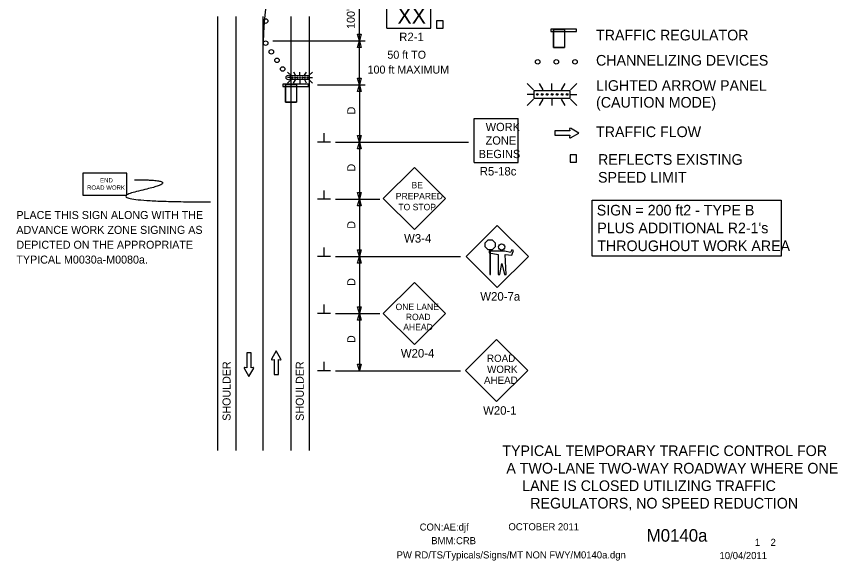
# Model space of a CAD drawing. Extents: x 16738 to 18485, y 7217 to 8213.
# Drawn here: x 16738 to 17456, y 7218 to 7694 of the extents above; entities that cross this region are included whole.
import ezdxf

# ---------------------------------------------------------------- set-up
doc = ezdxf.new("R2010")
doc.units = 0
for name, color, linetype in [('ALI_LEGAL_EX', 7, 'Continuous'), ('BORDER', 7, 'Continuous'), ('BORDER_SIGNAL_WO', 7, 'Continuous'), ('MT_SCRATCH_LEVEL_E', 7, 'Continuous'), ('PAVT_EDGE_EX', 7, 'Continuous'), ('TRAFFIC_SIGNS_PR', 7, 'Continuous'), ('TYPICAL_TEXT_DIMEN_EX', 7, 'Continuous'), ('TYPICAL_TEXT_DIMEN_PR', 7, 'Continuous')]:
    doc.layers.add(name, color=color, linetype=linetype)

msp = doc.modelspace()

# ---------------------------------------------------------------- linework, layer by layer
at = {"layer": 'ALI_LEGAL_EX'}
msp.add_line((16953.95, 7314.41), (16953.95, 7671.03), dxfattribs=at)
msp.add_line((16953.95, 7314.41), (16953.95, 7671.03), dxfattribs=at)
msp.add_arc((17174.73, 7671.79), 220.78, 142.68987, 180.19827, dxfattribs=at)
at = {"layer": 'MT_SCRATCH_LEVEL_E'}
for p, q in [((17222.13, 7593.96), (17208.87, 7593.96)), ((17208.87, 7593.96), (17208.87, 7590.22)), ((17222.13, 7593.96), (17208.87, 7593.96)), ((17208.87, 7593.96), (17208.87, 7590.22)), ((17221.81, 7595.74), (17222.13, 7593.96)), ((17221.81, 7595.74), (17222.13, 7593.96)), ((17229.74, 7592.11), (17222.5, 7596.22)), ((17229.74, 7592.11), (17222.5, 7596.22)), ((17222.5, 7587.96), (17229.74, 7592.11)), ((17222.5, 7587.96), (17229.74, 7592.11)), ((17208.87, 7590.22), (17222.13, 7590.22)), ((17208.87, 7590.22), (17222.13, 7590.22)), ((17222.13, 7590.22), (17221.81, 7588.44)), ((17222.13, 7590.22), (17221.81, 7588.44)), ((16943.27, 7399.92), (16939.52, 7399.92)), ((16939.52, 7399.92), (16939.52, 7386.67)), ((16943.27, 7399.92), (16939.52, 7399.92)), ((16939.52, 7399.92), (16939.52, 7386.67)), ((16943.27, 7386.67), (16943.27, 7399.92)), ((16943.27, 7386.67), (16943.27, 7399.92)), ((16965.24, 7401.61), (16961.12, 7394.37)), ((16965.24, 7401.61), (16961.12, 7394.37)), ((16969.38, 7394.37), (16965.24, 7401.61)), ((16969.38, 7394.37), (16965.24, 7401.61)), ((16961.61, 7393.69), (16963.38, 7394)), ((16961.61, 7393.69), (16963.38, 7394)), ((16963.38, 7394), (16963.38, 7380.74)), ((16963.38, 7394), (16963.38, 7380.74)), ((16967.12, 7380.74), (16967.12, 7394)), ((16967.12, 7394), (16968.9, 7393.69)), ((16967.12, 7380.74), (16967.12, 7394)), ((16967.12, 7394), (16968.9, 7393.69)), ((16937.27, 7386.3), (16941.41, 7379.06)), ((16937.27, 7386.3), (16941.41, 7379.06)), ((16939.52, 7386.67), (16937.75, 7386.98)), ((16939.52, 7386.67), (16937.75, 7386.98)), ((16941.41, 7379.06), (16945.53, 7386.3)), ((16941.41, 7379.06), (16945.53, 7386.3)), ((16945.04, 7386.98), (16943.27, 7386.67)), ((16945.04, 7386.98), (16943.27, 7386.67)), ((16963.38, 7380.74), (16967.12, 7380.74)), ((16963.38, 7380.74), (16967.12, 7380.74))]:
    msp.add_line(p, q, dxfattribs=at)
for centre, start, end in [((17222.27, 7595.81), 60.42484, 189.96381), ((17222.27, 7595.81), 60.42484, 189.96381), ((17222.27, 7588.37), 170.03619, 299.77312), ((17222.27, 7588.37), 170.03619, 299.77312), ((16961.53, 7394.15), 150.42484, 279.96381), ((16961.53, 7394.15), 150.42484, 279.96381), ((16968.97, 7394.15), 260.03619, 29.77312), ((16968.97, 7394.15), 260.03619, 29.77312), ((16937.68, 7386.52), 80.03619, 209.77312), ((16937.68, 7386.52), 80.03619, 209.77312), ((16945.12, 7386.52), 330.42484, 99.96381), ((16945.12, 7386.52), 330.42484, 99.96381)]:
    msp.add_arc(centre, 0.463, start, end, dxfattribs=at)
at = {"layer": 'PAVT_EDGE_EX'}
for p, q in [((16913.95, 7694.12), (16913.95, 7314.41)), ((16929.95, 7694.12), (16929.95, 7314.41)), ((16953.95, 7314.41), (16953.95, 7694.12)), ((16977.95, 7694.12), (16977.95, 7314.41)), ((16993.95, 7694.12), (16993.95, 7314.41))]:
    msp.add_line(p, q, dxfattribs=at)
for points in [[(16953.95, 7614.41), (16953.95, 7639.41)], [(16953.95, 7514.41), (16953.95, 7539.41)], [(16953.95, 7414.41), (16953.95, 7439.41)], [(16953.95, 7314.41), (16953.95, 7339.41)]]:
    msp.add_lwpolyline(points, dxfattribs=at)
at = {"layer": 'TRAFFIC_SIGNS_PR'}
for p, q in [((17062.1, 7683.95), (17062.1, 7731.95)), ((17100.5, 7683.95), (17100.5, 7731.95)), ((17062.1, 7683.95), (17100.5, 7683.95)), ((17207.84, 7682.59), (17207.84, 7666.99)), ((17217.43, 7682.59), (17217.43, 7666.99)), ((17207.84, 7666.99), (17217.43, 7666.99)), ((16975.05, 7645.45), (16977.87, 7642.64)), ((16982.14, 7642.64), (16980.51, 7645.46)), ((16985.95, 7642.64), (16985.95, 7645.46)), ((16990.09, 7642.64), (16991.71, 7645.46)), ((16994.04, 7642.64), (16996.86, 7645.46)), ((16973.43, 7634.58), (16973.43, 7618.97)), ((16977.87, 7640.61), (16975.05, 7640.61)), ((16975.05, 7635.76), (16977.87, 7638.57)), ((16979.5, 7640.61), (16979.5, 7640.61)), ((16980.48, 7635.75), (16982.11, 7638.57)), ((16981.68, 7640.61), (16981.68, 7640.61)), ((16983.01, 7634.58), (16983.01, 7618.97)), ((16983.85, 7640.61), (16983.85, 7640.61)), ((16985.95, 7638.57), (16985.95, 7635.75)), ((16986.03, 7640.61), (16986.03, 7640.61)), ((16988.2, 7640.61), (16988.2, 7640.61)), ((16991.74, 7635.75), (16990.11, 7638.57)), ((16990.37, 7640.61), (16990.37, 7640.61)), ((16992.55, 7640.61), (16992.55, 7640.61)), ((16994.04, 7640.61), (16996.86, 7640.61)), ((16994.04, 7638.57), (16996.86, 7635.75)), ((17184.6, 7635.55), (17190.23, 7629.92)), ((17198.77, 7629.92), (17195.51, 7635.56)), ((17206.4, 7629.92), (17206.4, 7635.56)), ((17214.67, 7629.92), (17217.93, 7635.56)), ((17222.57, 7629.92), (17228.22, 7635.56)), ((17190.23, 7625.85), (17184.6, 7625.85)), ((17184.6, 7616.15), (17190.23, 7621.79)), ((17193.51, 7625.85), (17193.51, 7625.85)), ((17195.47, 7616.15), (17198.72, 7621.79)), ((17197.86, 7625.85), (17197.86, 7625.85)), ((17202.2, 7625.85), (17202.2, 7625.85)), ((17206.4, 7621.79), (17206.4, 7616.15)), ((17206.55, 7625.85), (17206.55, 7625.85)), ((17210.9, 7625.85), (17210.9, 7625.85)), ((17217.98, 7616.15), (17214.72, 7621.79)), ((17215.25, 7625.85), (17215.25, 7625.85)), ((17219.59, 7625.85), (17219.59, 7625.85)), ((17222.57, 7625.85), (17228.22, 7625.85)), ((17222.57, 7621.79), (17228.22, 7616.15)), ((16973.43, 7618.97), (16983.01, 7618.97)), ((17138.41, 7566.43), (17138.41, 7604.83)), ((17138.41, 7604.83), (17176.81, 7604.83)), ((17176.81, 7566.43), (17176.81, 7604.83)), ((17086.05, 7562.01), (17058.9, 7534.85)), ((17113.21, 7534.85), (17086.05, 7562.01)), ((17138.41, 7566.43), (17176.81, 7566.43)), ((17058.9, 7534.85), (17086.05, 7507.7)), ((17086.05, 7507.7), (17113.21, 7534.85)), ((17158.57, 7511.24), (17131.42, 7484.08)), ((17185.72, 7484.08), (17158.57, 7511.24)), ((17131.42, 7484.08), (17158.57, 7456.93)), ((17158.57, 7456.93), (17185.72, 7484.08)), ((17086.05, 7461.49), (17058.9, 7434.34)), ((17113.21, 7434.34), (17086.05, 7461.49)), ((17058.9, 7434.34), (17086.05, 7407.18)), ((17086.05, 7407.18), (17113.21, 7434.34)), ((17158, 7411.45), (17130.85, 7384.3)), ((17185.15, 7384.3), (17158, 7411.45)), ((17130.85, 7384.3), (17158, 7357.15)), ((17158, 7357.15), (17185.15, 7384.3))]:
    msp.add_line(p, q, dxfattribs=at)
for points in [[(17105.51, 7683.95), (17111.11, 7683.95), (17111.11, 7690.12), (17105.51, 7690.12)], [(17227.83, 7682.92), (17205.45, 7682.92), (17205.45, 7680.82), (17227.83, 7680.82)], [(17207.84, 7682.59), (17217.43, 7682.59), (17217.43, 7666.99), (17207.84, 7666.99)], [(16993.81, 7638.81), (16978.1, 7638.81), (16978.1, 7642.4), (16993.81, 7642.4)], [(16993.42, 7634.91), (16971.04, 7634.91), (16971.04, 7632.81), (16993.42, 7632.81)], [(16973.43, 7634.58), (16983.01, 7634.58), (16983.01, 7618.97), (16973.43, 7618.97)], [(17222.11, 7622.25), (17190.7, 7622.25), (17190.7, 7629.45), (17222.11, 7629.45)], [(17222.31, 7566.76), (17227.9, 7566.76), (17227.9, 7572.93), (17222.31, 7572.93)], [(16796.16, 7537.72), (16834.56, 7537.72), (16834.56, 7556.92), (16796.16, 7556.92)], [(17150.53, 7498.72), (17154.21, 7498.72), (17156.81, 7496.12), (17156.81, 7492.45), (17154.21, 7489.85), (17150.53, 7489.85), (17147.94, 7492.44), (17147.94, 7496.12)], [(17165.25, 7488.81), (17151.43, 7488.81), (17151.43, 7487.31), (17159.4, 7485.85), (17159.4, 7468.45), (17160.9, 7468.45), (17162.4, 7478.05), (17164.8, 7468.45), (17166.3, 7468.45), (17165.4, 7485.85), (17171.4, 7485.25), (17172.6, 7489.45), (17171.14, 7489.82), (17170.24, 7487.71)], [(17152.07, 7489.85), (17152.07, 7468.47), (17152.67, 7468.47), (17152.67, 7489.85)]]:
    msp.add_lwpolyline(points, close=True, dxfattribs=at)
for centre, radius in [((16955.95, 7690.07), 2), ((16955.99, 7670.68), 2), ((16960.96, 7663.17), 2), ((16965.93, 7655.67), 2), ((17193.89, 7654.42), 2), ((17210.19, 7654.42), 2), ((17226.49, 7654.42), 2), ((16970.9, 7648.16), 2), ((16975.87, 7640.66), 2), ((16979.52, 7640.61), 0.379), ((16981.68, 7640.61), 0.379), ((16983.85, 7640.61), 0.379), ((16986.02, 7640.61), 0.379), ((16988.2, 7640.61), 0.379), ((16990.37, 7640.61), 0.379), ((16992.54, 7640.61), 0.379), ((17193.55, 7625.85), 0.758), ((17197.85, 7625.85), 0.758), ((17202.2, 7625.85), 0.758), ((17206.55, 7625.85), 0.758), ((17210.9, 7625.85), 0.758), ((17215.24, 7625.85), 0.758), ((17219.59, 7625.85), 0.758), ((17162.38, 7492.42), 2.7)]:
    msp.add_circle(centre, radius, dxfattribs=at)
msp.add_open_spline([(16841.19, 7551.25), (16888.42, 7551.25), (16803.4, 7531.91), (16907.67, 7531.91)], degree=2, dxfattribs=at)
at = {"layer": 'TYPICAL_TEXT_DIMEN_EX'}
msp.add_lwpolyline([(17241.58, 7533.37), (17406.76, 7533.37), (17406.76, 7484.34), (17241.58, 7484.34)], close=True, dxfattribs=at)
at = {"layer": 'TYPICAL_TEXT_DIMEN_PR'}
for p, q in [((17037.95, 7672.69), (17037.95, 7707.54)), ((17037.95, 7672.69), (17036.38, 7678.56)), ((17036.38, 7678.56), (17037.95, 7678.56)), ((17037.95, 7678.56), (17039.52, 7678.56)), ((17039.52, 7678.56), (17037.95, 7672.69)), ((16962.26, 7672.69), (17042.95, 7672.69)), ((17036.38, 7666.83), (17037.95, 7672.69)), ((17036.38, 7666.83), (17037.95, 7672.69)), ((17037.95, 7634.19), (17037.95, 7672.69)), ((17037.95, 7672.69), (17039.52, 7666.83)), ((17037.95, 7672.69), (17039.52, 7666.83)), ((17037.95, 7666.83), (17036.38, 7666.83)), ((17037.95, 7666.83), (17036.38, 7666.83)), ((17039.52, 7666.83), (17037.95, 7666.83)), ((17039.52, 7666.83), (17037.95, 7666.83)), ((17001.32, 7634.19), (17042.95, 7634.19)), ((17037.95, 7634.19), (17036.38, 7640.05)), ((17036.38, 7640.05), (17037.95, 7640.05)), ((17037.95, 7634.19), (17036.38, 7640.05)), ((17036.38, 7640.05), (17037.95, 7640.05)), ((17036.38, 7628.33), (17037.95, 7634.19)), ((17036.38, 7628.33), (17037.95, 7634.19)), ((17037.95, 7640.05), (17039.52, 7640.05)), ((17039.52, 7640.05), (17037.95, 7634.19)), ((17037.95, 7640.05), (17039.52, 7640.05)), ((17039.52, 7640.05), (17037.95, 7634.19)), ((17037.95, 7634.19), (17037.95, 7584.19)), ((17037.95, 7634.19), (17039.52, 7628.33)), ((17037.95, 7634.19), (17039.52, 7628.33)), ((17037.95, 7628.33), (17036.38, 7628.33)), ((17037.95, 7628.33), (17036.38, 7628.33)), ((17039.52, 7628.33), (17037.95, 7628.33)), ((17039.52, 7628.33), (17037.95, 7628.33)), ((17007.07, 7584.19), (17007.07, 7591.97)), ((17012.7, 7584.19), (17001.45, 7584.19)), ((17016.95, 7584.19), (17133.46, 7584.19)), ((17037.95, 7584.19), (17036.38, 7590.05)), ((17036.38, 7590.05), (17037.95, 7590.05)), ((17037.95, 7584.19), (17036.38, 7590.05)), ((17036.38, 7590.05), (17037.95, 7590.05)), ((17036.38, 7578.33), (17037.95, 7584.19)), ((17036.38, 7578.33), (17037.95, 7584.19)), ((17037.95, 7590.05), (17039.52, 7590.05)), ((17039.52, 7590.05), (17037.95, 7584.19)), ((17037.95, 7590.05), (17039.52, 7590.05)), ((17039.52, 7590.05), (17037.95, 7584.19)), ((17037.95, 7584.19), (17039.52, 7578.33)), ((17037.95, 7584.19), (17039.52, 7578.33)), ((17037.95, 7584.19), (17037.95, 7534.19)), ((17037.95, 7578.33), (17036.38, 7578.33)), ((17037.95, 7578.33), (17036.38, 7578.33)), ((17039.52, 7578.33), (17037.95, 7578.33)), ((17039.52, 7578.33), (17037.95, 7578.33)), ((17007.07, 7534.19), (17007.07, 7541.97)), ((17012.7, 7534.19), (17001.45, 7534.19)), ((17016.95, 7534.19), (17055.95, 7534.19)), ((17037.95, 7534.19), (17036.38, 7540.05)), ((17036.38, 7540.05), (17037.95, 7540.05)), ((17037.95, 7534.19), (17036.38, 7540.05)), ((17036.38, 7540.05), (17037.95, 7540.05)), ((17036.38, 7528.33), (17037.95, 7534.19)), ((17036.38, 7528.33), (17037.95, 7534.19)), ((17037.95, 7540.05), (17039.52, 7540.05)), ((17039.52, 7540.05), (17037.95, 7534.19)), ((17037.95, 7540.05), (17039.52, 7540.05)), ((17039.52, 7540.05), (17037.95, 7534.19)), ((17037.95, 7534.19), (17037.95, 7484.19)), ((17037.95, 7534.19), (17039.52, 7528.33)), ((17037.95, 7534.19), (17039.52, 7528.33)), ((17037.95, 7528.33), (17036.38, 7528.33)), ((17037.95, 7528.33), (17036.38, 7528.33)), ((17039.52, 7528.33), (17037.95, 7528.33)), ((17039.52, 7528.33), (17037.95, 7528.33)), ((17007.07, 7484.19), (17007.07, 7491.97)), ((17037.95, 7484.19), (17036.38, 7490.05)), ((17036.38, 7490.05), (17037.95, 7490.05)), ((17037.95, 7484.19), (17036.38, 7490.05)), ((17036.38, 7490.05), (17037.95, 7490.05)), ((17037.95, 7490.05), (17039.52, 7490.05)), ((17039.52, 7490.05), (17037.95, 7484.19)), ((17037.95, 7490.05), (17039.52, 7490.05)), ((17039.52, 7490.05), (17037.95, 7484.19)), ((17012.7, 7484.19), (17001.45, 7484.19)), ((17016.95, 7484.19), (17126.34, 7484.19)), ((17036.38, 7478.33), (17037.95, 7484.19)), ((17036.38, 7478.33), (17037.95, 7484.19)), ((17037.95, 7484.19), (17037.95, 7434.19)), ((17037.95, 7484.19), (17039.52, 7478.33)), ((17037.95, 7484.19), (17039.52, 7478.33)), ((17037.95, 7478.33), (17036.38, 7478.33)), ((17037.95, 7478.33), (17036.38, 7478.33)), ((17039.52, 7478.33), (17037.95, 7478.33)), ((17039.52, 7478.33), (17037.95, 7478.33)), ((17007.07, 7434.19), (17007.07, 7441.97)), ((17037.95, 7434.19), (17036.38, 7440.05)), ((17036.38, 7440.05), (17037.95, 7440.05)), ((17037.95, 7434.19), (17036.38, 7440.05)), ((17036.38, 7440.05), (17037.95, 7440.05)), ((17037.95, 7440.05), (17039.52, 7440.05)), ((17039.52, 7440.05), (17037.95, 7434.19)), ((17037.95, 7440.05), (17039.52, 7440.05)), ((17039.52, 7440.05), (17037.95, 7434.19)), ((17012.7, 7434.19), (17001.45, 7434.19)), ((17016.95, 7434.19), (17055.95, 7434.19)), ((17036.38, 7428.33), (17037.95, 7434.19)), ((17036.38, 7428.33), (17037.95, 7434.19)), ((17037.95, 7434.19), (17037.95, 7384.19)), ((17037.95, 7434.19), (17039.52, 7428.33)), ((17037.95, 7434.19), (17039.52, 7428.33)), ((17037.95, 7428.33), (17036.38, 7428.33)), ((17037.95, 7428.33), (17036.38, 7428.33)), ((17039.52, 7428.33), (17037.95, 7428.33)), ((17039.52, 7428.33), (17037.95, 7428.33)), ((17007.07, 7384.19), (17007.07, 7391.97)), ((17037.95, 7384.19), (17036.38, 7390.05)), ((17036.38, 7390.05), (17037.95, 7390.05)), ((17037.95, 7384.19), (17036.38, 7390.05)), ((17036.38, 7390.05), (17037.95, 7390.05)), ((17037.95, 7390.05), (17039.52, 7390.05)), ((17039.52, 7390.05), (17037.95, 7384.19)), ((17037.95, 7390.05), (17039.52, 7390.05)), ((17039.52, 7390.05), (17037.95, 7384.19)), ((17012.7, 7384.19), (17001.45, 7384.19)), ((17016.95, 7384.19), (17126.34, 7384.19))]:
    msp.add_line(p, q, dxfattribs=at)

# ---------------------------------------------------------------- texts
at = {"layer": 'BORDER'}
for s, p in [('TYPICAL TEMPORARY TRAFFIC CONTROL FOR', (17162.96, 7309.55)), ('A TWO-LANE TWO-WAY ROADWAY WHERE ONE', (17166.51, 7294.25)), ('LANE IS CLOSED UTILIZING TRAFFIC', (17180.38, 7278.95)), ('REGULATORS, NO SPEED REDUCTION', (17187.41, 7263.65))]:
    msp.add_text(s, height=9.3, dxfattribs=at).set_placement(p)
at = {"layer": 'BORDER_SIGNAL_WO'}
for s, height, p in [('CON:AE:djf', 6.2, (17090.69, 7244.31)), ('    OCTOBER 2011    ', 6.2, (17159.08, 7244.59)), ('BMM:CRB   ', 6.2, (17100.81, 7232.42)), ('    M0140a   ', 11, (17272.86, 7234.63)), (' 1    2 ', 6.2, (17381.45, 7230.95)), ('PW RD/TS/Typicals/Signs/MT NON FWY/M0140a.dgn    ', 6.2, (17070.55, 7219.96)), ('10/04/2011    ', 6.2, (17352.93, 7219.38))]:
    msp.add_text(s, height=height, dxfattribs=at).set_placement(p)
at = {"layer": 'TRAFFIC_SIGNS_PR'}
for s, height, p in [('XX', 14.031, (17071.21, 7687.7)), ('R2-1', 7.44, (17072.77, 7672.51)), ('WORK', 7.217, (17148.41, 7593.8)), ('ZONE', 7.217, (17148.29, 7581.99)), ('BEGINS', 7.217, (17142.22, 7570.18)), ('R5-18c', 7.44, (17143.22, 7554.99)), ('END', 3.831, (16811.17, 7548.85)), ('BE', 5.6, (17083.56, 7543.78)), ('ROAD WORK', 3.831, (16799.77, 7542.46)), ('PREPARED', 5.6, (17069.8, 7534.18)), ('TO STOP', 5.6, (17072.08, 7524.58)), ('PLACE THIS SIGN ALONG WITH THE', 7, (16738.01, 7516.89)), ('ADVANCE WORK ZONE SIGNING AS', 7, (16738.01, 7503.89)), ('DEPICTED ON THE APPROPRIATE', 7, (16738.01, 7490.89)), ('W3-4', 7.44, (17077.06, 7496.26)), ('TYPICAL M0030a-M0080a.', 7, (16738.01, 7477.89)), ('W20-7a', 7.44, (17143.71, 7445.49)), ('ONE LANE', 5.6, (17069.64, 7437.21)), ('ROAD', 5.6, (17078.59, 7428.41)), ('AHEAD', 5.6, (17076.35, 7419.61)), ('W20-4', 7.44, (17074.23, 7395.74)), ('ROAD', 6.4, (17149.54, 7391.84)), ('WORK', 6.4, (17149.65, 7382.24)), ('AHEAD', 6.4, (17146.96, 7372.64)), ('W20-1', 7.44, (17146.17, 7345.71))]:
    msp.add_text(s, height=height, dxfattribs=at).set_placement(p)
at = {"layer": 'TYPICAL_TEXT_DIMEN_EX'}
for s, p in [('TRAFFIC REGULATOR', (17244.92, 7673.14)), ('CHANNELIZING DEVICES', (17244.92, 7651.09)), ('LIGHTED ARROW PANEL', (17244.92, 7629.03)), ('(CAUTION MODE)', (17244.92, 7614.34)), ('TRAFFIC FLOW', (17244.92, 7588.53)), ('REFLECTS EXISTING ', (17246.68, 7564.33)), ('SPEED LIMIT', (17246.68, 7548.73)), ('SIGN = 200 ft2 - TYPE B', (17245.52, 7519.97)), ("PLUS ADDITIONAL R2-1's", (17246.03, 7504.41)), ('THROUGHOUT WORK AREA', (17246.03, 7488.81))]:
    msp.add_text(s, height=9.3, dxfattribs=at).set_placement(p)
at = {"layer": 'TYPICAL_TEXT_DIMEN_PR'}
for s, p in [("100'", (17033.98, 7683.2)), ('D', (17034.37, 7608.41)), ('D', (17034.37, 7558.41)), ('D', (17034.37, 7508.41)), ('D', (17034.37, 7458.41)), ('D', (17034.37, 7408.41)), ('SHOULDER', (16925.3, 7340.38)), ('SHOULDER', (16989.35, 7340.38))]:
    msp.add_text(s, height=7, rotation=90, dxfattribs=at).set_placement(p)
for s, p in [('50 ft TO', (17062.45, 7657.1)), ('100 ft MAXIMUM', (17045.14, 7644.1))]:
    msp.add_text(s, height=7, dxfattribs=at).set_placement(p)

doc.saveas('drawing.dxf')
